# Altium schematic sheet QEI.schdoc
size 297 x 209 mm; Symbol: Drawing-Symbol_A4; Company: 嘉立创EDA; Version: V1.0; Page Size: A4; @Project Name: 西柚在学EtherCAT; @Update Date: 2026-08-01; @Create Date: 2026-08-01; Device: Drawing-Symbol_A4; @Board Name: HPM5E3YIVK1_2; @Page Name: P1; @Create Time: 18:03:03; @Page Count: 12; @Page No: 12; @Schematic Name: HPM5E3YIVK1_2; @Update Time: 18:03:03; @Assembly Variant: Basic; Border: 1; Title Block Position: 3; Size: A4; Width: 1170; Height: 825; Region Start: 1; X Region Count: 6; Y Region Count: 4; Blade Width: 10
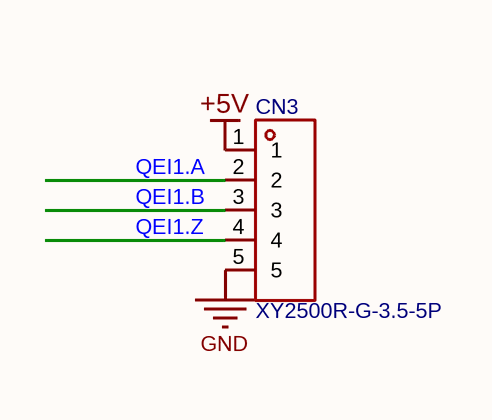
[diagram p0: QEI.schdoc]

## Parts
CN3  XY2500R-G-3.5-5P  [CONN-TH_XY2500R-G-3.5-5P]

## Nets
+5V: CN3.1
GND: CN3.5
QEI1.A: CN3.2
QEI1.B: CN3.3
QEI1.Z: CN3.4

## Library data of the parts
CN3 = XY2500R-G-3.5-5P: 连接器类型:板端/插座-闭口;结构:1x5P;间距:3.5mm;颜色:绿色;安装方式:弯插;排数:1;每排PIN数:5;额定电流:8A;额定电压:300V;工作温度:-;; Manufacturer: XINLAIYA(新莱亚); 3D Model: 4d11d251c1214fde94178c03f7dbb6e00819f05c4eef4c71ace90d822a990e87; 3D Model Transform: 728.345,358.267,0,0,0,0,0,124.016,-137.795; Number of Positions or Pins: 1x5P; Pitch: 3.5mm; Number of PINs Per Row: 5; Current Rating: 8A; Voltage Rating (Max): 300V; AddInBom: yes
